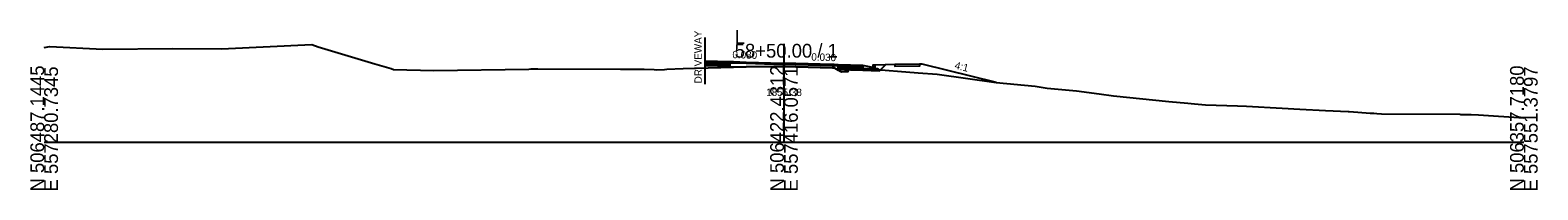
# Model space of a CAD drawing. Extents: x -26 to 4603, y -10 to 4703.
# Drawn here: x 1997.2 to 2302.8, y 3865.3 to 3897.8 of the extents above; entities that cross this region are included whole.
import ezdxf

# ---------------------------------------------------------------- set-up
doc = ezdxf.new("R2010")
doc.units = 0
for name, color, linetype in [('Default', 7, 'Continuous'), ('Exist Cross Section Cell', 7, 'Continuous'), ('Exist XS Ground Line', 7, 'Continuous'), ('Prop CMT Pvmt Course 1', 7, 'Continuous'), ('Prop CMT Pvmt Course 2', 7, 'Continuous'), ('Prop CMT Pvmt Course 3', 7, 'Continuous'), ('Prop CMT Pvmt Milling', 7, 'Continuous'), ('Prop CMT Shear Line', 7, 'Continuous'), ('Prop CMT Shld Paved Course 2', 7, 'Continuous'), ('Prop CMT Subgrade Earthwork', 7, 'Continuous'), ('Prop Conc 4in Sidewalk', 7, 'Continuous'), ('Prop Conc Curb and Gutter', 7, 'Continuous'), ('Prop Corridor Mesh Bottom', 7, 'Continuous'), ('Prop XS Finish Grade', 7, 'Continuous'), ('Prop XS Label Text', 7, 'Continuous'), ('Prop XS Shear Point Element', 7, 'Continuous'), ('Prop XS Shear Point Label', 7, 'Continuous'), ('Prop XS SS Elevation Text', 7, 'Continuous')]:
    doc.layers.add(name, color=color, linetype=linetype)

msp = doc.modelspace()

# ---------------------------------------------------------------- linework, layer by layer
at = {"layer": 'Exist Cross Section Cell'}
for p, q in [((2150, 3875), (2150, 3895)), ((2000, 3875), (2150, 3875)), ((2150, 3875), (2300, 3875))]:
    msp.add_line(p, q, dxfattribs=at)
at = {"layer": 'Exist XS Ground Line'}
msp.add_lwpolyline([(2000, 3894.24), (2001.16, 3894.45), (2011.88, 3893.95), (2026.02, 3894.03), (2035.95, 3894.02), (2054.27, 3894.9), (2055.54, 3894.42), (2067.04, 3890.97), (2070.37, 3889.96), (2070.84, 3889.8), (2079.02, 3889.61), (2098.26, 3889.86), (2098.64, 3889.89), (2098.86, 3889.9), (2099.03, 3889.9), (2100.11, 3889.89), (2116.84, 3889.87), (2120.23, 3889.86), (2120.32, 3889.87), (2120.35, 3889.87), (2121.63, 3889.86), (2123.67, 3889.77), (2124.17, 3889.74), (2125.8, 3889.81), (2126.21, 3889.84), (2129.56, 3890), (2137.16, 3890.2), (2139.12, 3890.26), (2139.76, 3890.27), (2142.34, 3890.31), (2149.76, 3890.38), (2152.41, 3890.32), (2159.8, 3890.12), (2160.17, 3890.11), (2160.65, 3889.83), (2161.67, 3889.29), (2162.24, 3889.35), (2163.01, 3889.36), (2163.1, 3889.55), (2163.2, 3889.89), (2165.64, 3889.9), (2166.92, 3889.93), (2167.1, 3889.89), (2177.22, 3889.1), (2181.02, 3888.84), (2193.02, 3887.13), (2200.89, 3886.39), (2203.36, 3885.98), (2209.33, 3885.45), (2213.9, 3884.82), (2216.82, 3884.42), (2227.99, 3883.31), (2231.86, 3882.96), (2233.21, 3882.82), (2235.44, 3882.61), (2241.94, 3882.37), (2243.8, 3882.3), (2250.99, 3881.92), (2254.57, 3881.72), (2259.77, 3881.47), (2264.36, 3881.24), (2264.56, 3881.23), (2266.34, 3881.11), (2268.81, 3880.94), (2269.56, 3880.88), (2270.21, 3880.84), (2271.12, 3880.8), (2287, 3880.68), (2287.06, 3880.68), (2287.12, 3880.68), (2287.15, 3880.67), (2287.91, 3880.65), (2289.35, 3880.61), (2290.8, 3880.55), (2300, 3879.99)], dxfattribs=at)
at = {"layer": 'Prop CMT Pvmt Course 1'}
for points in [[(2134, 3891.55), (2139, 3891.4), (2139, 3891.4), (2139, 3891.15), (2134, 3891.3), (2134, 3891.3), (2134, 3891.55), (2134, 3891.55), (2134, 3891.55)], [(2150, 3891.07), (2150, 3891.07), (2150, 3891.07), (2150, 3890.38), (2150, 3890.38), (2149.76, 3890.38), (2149.76, 3890.38), (2142.34, 3890.31), (2142.34, 3890.31), (2139.76, 3890.27), (2139.12, 3890.26), (2139.12, 3890.26), (2139, 3890.25), (2139, 3891.4), (2139, 3891.4), (2139.12, 3891.4), (2139.12, 3891.4), (2139.76, 3891.38), (2142.34, 3891.3), (2142.34, 3891.3), (2149.76, 3891.08), (2149.76, 3891.08), (2150, 3891.07)], [(2160.65, 3890.75), (2160.17, 3890.77), (2159.8, 3890.78), (2159.8, 3890.78), (2159.8, 3890.78), (2152.41, 3891), (2152.41, 3891), (2150, 3891.07), (2150, 3891.07), (2150, 3890.38), (2152.41, 3890.32), (2152.41, 3890.32), (2159.8, 3890.12), (2159.8, 3890.12), (2159.8, 3890.12), (2160.17, 3890.11), (2160.65, 3889.83), (2160.65, 3889.83), (2161, 3889.64), (2161, 3890.74), (2161, 3890.74), (2160.65, 3890.75), (2160.65, 3890.75)], [(2161, 3890.74), (2161, 3890.74), (2161, 3890.74), (2161, 3890.49), (2161, 3890.49), (2166, 3890.34), (2166, 3890.59), (2166, 3890.59), (2161, 3890.74)]]:
    msp.add_lwpolyline(points, dxfattribs=at)
at = {"layer": 'Prop CMT Pvmt Course 2'}
for points in [[(2134, 3891.3), (2139, 3891.15), (2139, 3891.15), (2139, 3890.82), (2134, 3890.97), (2134, 3890.97), (2134, 3891.3), (2134, 3891.3), (2134, 3891.3)], [(2161, 3890.49), (2161, 3890.49), (2161, 3890.49), (2161, 3890.16), (2161, 3890.16), (2166, 3890.01), (2166, 3890.34), (2166, 3890.34), (2161, 3890.49)]]:
    msp.add_lwpolyline(points, dxfattribs=at)
at = {"layer": 'Prop CMT Pvmt Course 3'}
for points in [[(2134, 3890.97), (2139, 3890.82), (2139, 3890.82), (2139, 3890.45), (2134, 3890.6), (2134, 3890.6), (2134, 3890.97), (2134, 3890.97), (2134, 3890.97)], [(2161, 3890.16), (2161, 3890.16), (2161, 3890.16), (2161, 3889.79), (2161, 3889.79), (2166, 3889.64), (2166, 3890.01), (2166, 3890.01), (2161, 3890.16)], [(2166, 3890.01), (2166, 3890.01), (2166, 3890.01), (2166, 3889.64), (2166, 3889.64), (2169.39, 3889.53), (2169, 3889.92), (2169, 3889.92), (2166, 3890.01)]]:
    msp.add_lwpolyline(points, dxfattribs=at)
at = {"layer": 'Prop CMT Pvmt Milling'}
for points in [[(2139, 3890.25), (2139.12, 3890.26), (2139.12, 3890.26), (2139.76, 3890.27), (2142.34, 3890.31), (2142.34, 3890.31), (2149.76, 3890.38), (2149.76, 3890.38), (2150, 3890.38), (2150, 3890.38)], [(2161, 3889.64), (2160.65, 3889.83), (2160.65, 3889.83), (2160.17, 3890.11), (2159.8, 3890.12), (2159.8, 3890.12), (2159.8, 3890.12), (2152.41, 3890.32), (2152.41, 3890.32), (2150, 3890.38)]]:
    msp.add_lwpolyline(points, dxfattribs=at)
at = {"layer": 'Prop CMT Shld Paved Course 2'}
for points in [[(2150, 3890.82), (2150, 3890.82), (2150, 3890.82), (2150, 3890.38), (2150, 3890.38), (2149.76, 3890.38), (2149.76, 3890.38), (2142.34, 3890.31), (2142.34, 3890.31), (2139.76, 3890.27), (2139.12, 3890.26), (2139.12, 3890.26), (2139, 3890.25), (2139, 3891.15), (2139, 3891.15), (2139.12, 3891.15), (2139.12, 3891.15), (2139.76, 3891.13), (2142.34, 3891.05), (2142.34, 3891.05), (2149.76, 3890.83), (2149.76, 3890.83), (2150, 3890.82)], [(2160.65, 3890.5), (2160.17, 3890.52), (2159.8, 3890.53), (2159.8, 3890.53), (2159.8, 3890.53), (2152.41, 3890.75), (2152.41, 3890.75), (2150, 3890.82), (2150, 3890.82), (2150, 3890.38), (2152.41, 3890.32), (2152.41, 3890.32), (2159.8, 3890.12), (2159.8, 3890.12), (2159.8, 3890.12), (2160.17, 3890.11), (2160.65, 3889.83), (2160.65, 3889.83), (2161, 3889.64), (2161, 3890.49), (2161, 3890.49), (2160.65, 3890.5), (2160.65, 3890.5)]]:
    msp.add_lwpolyline(points, dxfattribs=at)
at = {"layer": 'Prop CMT Subgrade Earthwork'}
for points in [[(2134, 3890.6), (2139, 3890.45)], [(2169.39, 3889.53), (2161, 3889.79), (2161, 3889.79)], [(2170.59, 3890.74), (2170.59, 3890.74), (2169.39, 3889.53)]]:
    msp.add_lwpolyline(points, dxfattribs=at)
at = {"layer": 'Prop Conc 4in Sidewalk'}
msp.add_lwpolyline([(2177.5, 3890.87), (2172.5, 3890.77), (2172.5, 3890.77), (2172.49, 3890.44), (2177.51, 3890.54), (2177.51, 3890.54), (2177.5, 3890.87), (2177.5, 3890.87), (2177.5, 3890.87)], dxfattribs=at)
at = {"layer": 'Prop Conc Curb and Gutter'}
msp.add_lwpolyline([(2166, 3890.59), (2166, 3890.59), (2166, 3890.59), (2166, 3890.01), (2166, 3890.01), (2168.5, 3889.94), (2168.5, 3890.69), (2168.5, 3890.69), (2168, 3890.69), (2168, 3890.69), (2168, 3890.69), (2168, 3890.19), (2166, 3890.59)], dxfattribs=at)
at = {"layer": 'Prop Corridor Mesh Bottom'}
msp.add_lwpolyline([(2166, 3890.59), (2166, 3890.34)], dxfattribs=at)
at = {"layer": 'Prop XS Finish Grade'}
for points in [[(2172.5, 3890.77), (2172.5, 3890.77), (2168.5, 3890.69)], [(2178, 3890.88), (2178, 3890.88), (2177.5, 3890.87)], [(2193.05, 3887.12), (2178, 3890.88), (2178, 3890.88)]]:
    msp.add_lwpolyline(points, dxfattribs=at)
at = {"layer": 'Prop XS Shear Point Element'}
msp.add_line((2134, 3886.79), (2134, 3896.28), dxfattribs=at)

# ---------------------------------------------------------------- texts
at = {"layer": 'Default'}
msp.add_text('-', height=0.0001, dxfattribs=at).set_placement((2000, 3875))
at = {"layer": 'Exist Cross Section Cell'}
for s, p in [('L', (2140, 3895)), ('58+50.00 / 1', (2140, 3892.2))]:
    msp.add_text(s, height=2.8, dxfattribs=at).set_placement(p)
for s, p in [('N 506487.1445', (2000, 3865)), ('E 557280.7345', (2002.8, 3865)), ('N 506422.4312', (2150, 3865)), ('E 557416.0571', (2152.8, 3865)), ('N 506357.7180', (2300, 3865)), ('E 557551.3797', (2302.8, 3865))]:
    msp.add_text(s, height=2.8, rotation=90, dxfattribs=at).set_placement(p)
at = {"layer": 'Prop CMT Shear Line'}
for p in [(2134, 3891.55), (2114.13, 3889.88), (2150, 3891.07), (2166, 3890.59), (2166, 3890.59), (2168, 3890.19), (2172.5, 3890.77), (2177.5, 3890.87), (2178, 3890.88), (2193.05, 3887.12)]:
    msp.add_text('X', height=0.0025, dxfattribs=at).set_placement(p)
at = {"layer": 'Prop XS Label Text'}
for s, rotation, p in [('0.030', 358.2816, (2139.52, 3892.09)), ('0.030', 358.2816, (2155.52, 3891.61)), ('4:1', 345.9638, (2184.5, 3889.98))]:
    msp.add_text(s, height=1.5, rotation=rotation, dxfattribs=at).set_placement(p)
at = {"layer": 'Prop XS Shear Point Label'}
msp.add_text('DRIVEWAY', height=1.5, rotation=90, dxfattribs=at).set_placement((2133.33, 3886.97))
at = {"layer": 'Prop XS SS Elevation Text'}
msp.add_text('1855.38', height=1.5, dxfattribs=at).set_placement((2146.38, 3884.4))

doc.saveas('drawing.dxf')
